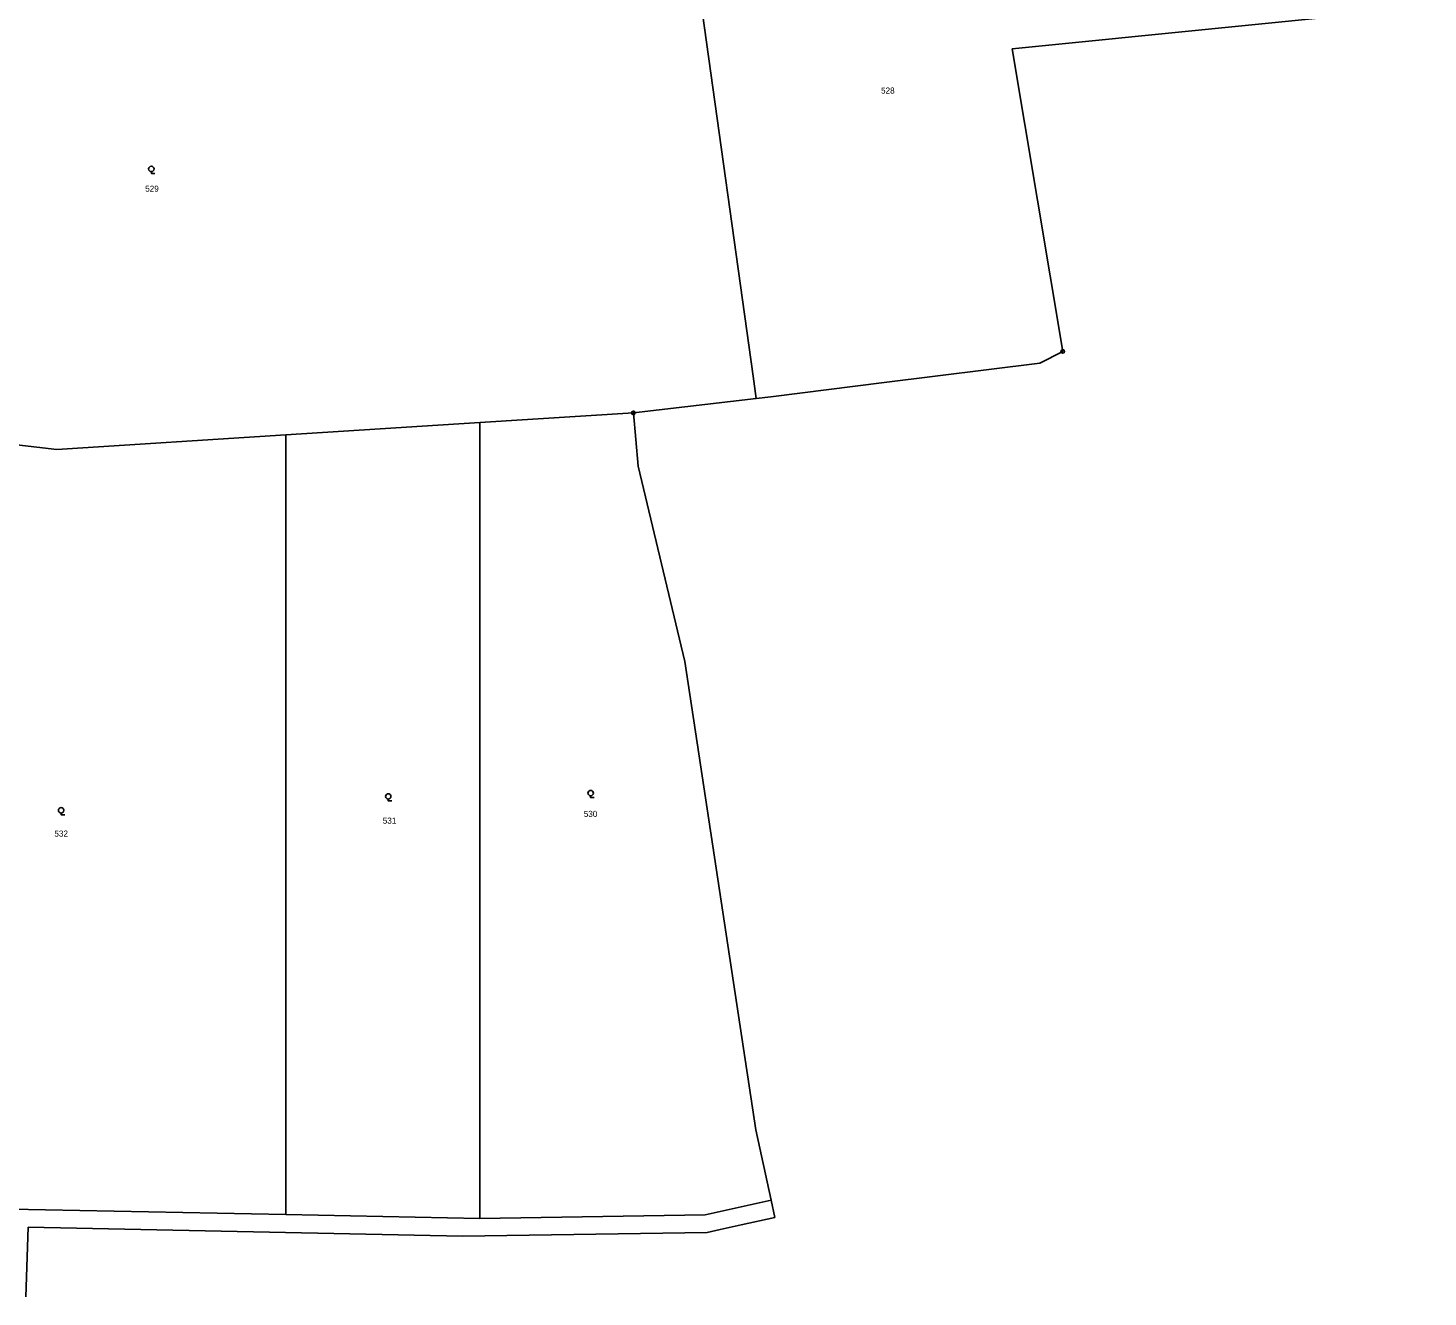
# Model space of a CAD drawing. Extents: x -759947 to -757003, y -1019641 to -1017100.
# Drawn here: x -757569.9 to -757179.2, y -1019592.6 to -1019238.4 of the extents above; entities that cross this region are included whole.
import ezdxf

# ---------------------------------------------------------------- set-up
doc = ezdxf.new("R2010")
doc.units = 0
doc.header["$LTSCALE"] = 0.68
for name, color, linetype, lineweight in [('1', 7, 'Continuous', 25), ('3', 7, 'Continuous', 25), ('8', 7, 'Continuous', 25)]:
    doc.layers.add(name, color=color, linetype=linetype, lineweight=lineweight)
doc.layers.add('2', color=7, linetype='Continuous')

msp = doc.modelspace()

# ---------------------------------------------------------------- linework, layer by layer
at = {"layer": '1'}
for p, q in [((-757367.57, -1019335.6), (-757384.96, -1019210.58)), ((-757179.15, -1019232.55), (-757295.25, -1019244.26)), ((-757295.25, -1019244.26), (-757281.11, -1019328.67)), ((-757281.11, -1019328.67), (-757287.49, -1019331.96)), ((-757331, -1019337.37), (-757287.49, -1019331.96)), ((-757366.71, -1019341.81), (-757367.57, -1019335.6)), ((-757362.63, -1019341.3), (-757331, -1019337.37)), ((-757366.71, -1019341.81), (-757400.96, -1019345.83)), ((-757366.71, -1019341.81), (-757362.63, -1019341.3)), ((-757443.83, -1019348.55), (-757400.96, -1019345.83)), ((-757399.64, -1019360.73), (-757400.96, -1019345.83)), ((-757497.95, -1019351.99), (-757443.83, -1019348.55)), ((-757443.83, -1019348.55), (-757443.83, -1019459.6)), ((-757593.85, -1019352.27), (-757561.94, -1019356.05)), ((-757561.94, -1019356.05), (-757497.95, -1019351.99)), ((-757497.95, -1019460.82), (-757497.95, -1019351.99)), ((-757399.64, -1019360.73), (-757386.57, -1019415.2)), ((-757386.57, -1019415.2), (-757366.8, -1019545.91)), ((-757443.83, -1019459.6), (-757443.83, -1019570.64)), ((-757497.95, -1019569.59), (-757497.95, -1019460.82)), ((-757362.49, -1019565.56), (-757366.8, -1019545.91)), ((-757362.49, -1019565.56), (-757380.94, -1019569.65)), ((-757362.49, -1019565.56), (-757361.44, -1019570.35)), ((-757497.95, -1019569.59), (-757574.64, -1019568.09)), ((-757443.83, -1019570.64), (-757497.95, -1019569.59)), ((-757380.94, -1019569.65), (-757443.83, -1019570.64)), ((-757570.51, -1019592.58), (-757569.89, -1019573.1)), ((-757448.69, -1019575.63), (-757569.89, -1019573.1)), ((-757380.37, -1019574.55), (-757376.77, -1019573.75)), ((-757376.77, -1019573.75), (-757370.9, -1019572.45)), ((-757370.9, -1019572.45), (-757361.44, -1019570.35)), ((-757380.37, -1019574.55), (-757448.69, -1019575.63))]:
    msp.add_line(p, q, dxfattribs=at)
at = {"layer": '3'}
for points in [[(-757535.52, -1019278.502), (-757535.52, -1019279), (-757534.519, -1019279)], [(-757469.39, -1019453.612), (-757469.39, -1019454.11), (-757468.389, -1019454.11)], [(-757412.89, -1019452.682), (-757412.89, -1019453.18), (-757411.889, -1019453.18)], [(-757560.71, -1019457.502), (-757560.71, -1019458), (-757559.709, -1019458)]]:
    msp.add_lwpolyline(points, dxfattribs=at)
for centre in [(-757535.5193, -1019277.7509), (-757469.3893, -1019452.8609), (-757412.8893, -1019451.9309), (-757560.7093, -1019456.7509)]:
    msp.add_circle(centre, 0.75, dxfattribs=at)
at = {"layer": '8'}
for centre, radius in [((-757281.11, -1019328.6699), 0.5), ((-757281.11, -1019328.6699), 0.0303), ((-757400.96, -1019345.8299), 0.5), ((-757400.96, -1019345.8299), 0.0303)]:
    msp.add_circle(centre, radius, dxfattribs=at)

# ---------------------------------------------------------------- texts
at = {"layer": '2'}
for s, p in [('528', (-757331.83, -1019256.715)), ('529', (-757537.24, -1019284.095)), ('531', (-757470.93, -1019460.475)), ('530', (-757414.82, -1019458.595)), ('532', (-757562.59, -1019464.095))]:
    msp.add_text(s, height=1.7, dxfattribs=at).set_placement(p)

doc.saveas('drawing.dxf')
